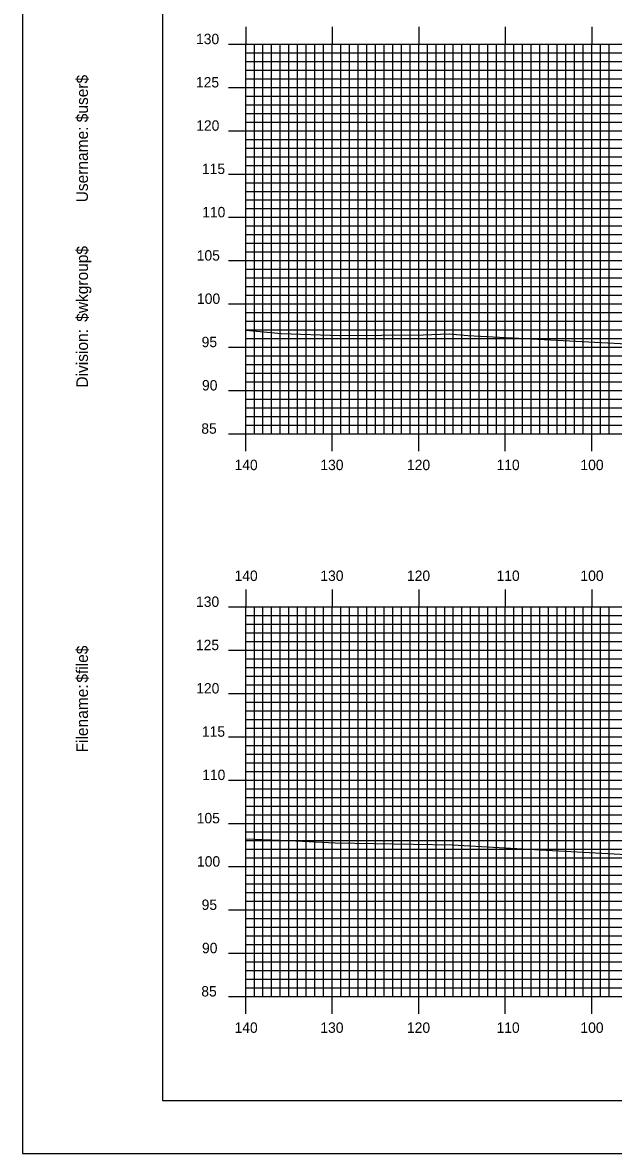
# Model space of a CAD drawing. Extents: x 1785795 to 1786139, y 442591 to 442811.
# Drawn here: x 1785795.3 to 1785863.6, y 442590.5 to 442721.2 of the extents above; entities that cross this region are included whole.
import ezdxf

# ---------------------------------------------------------------- set-up
doc = ezdxf.new("R2010")
doc.units = 0
for name, color, linetype in [('BORDER', 7, 'Continuous'), ('H_V ANNOTATION', 7, 'Continuous'), ('MAJOR', 7, 'Continuous'), ('MINOR', 7, 'Continuous'), ('PLOT BOUNDARY', 7, 'Continuous'), ('S_Roadway_Centerline', 7, 'Continuous')]:
    doc.layers.add(name, color=color, linetype=linetype)

msp = doc.modelspace()

# ---------------------------------------------------------------- linework, layer by layer
at = {"layer": 'BORDER'}
msp.add_lwpolyline([(1785811.45, 442596.67), (1786131.45, 442596.67), (1786131.45, 442806.67), (1785811.45, 442806.67)], close=True, dxfattribs=at)
at = {"layer": 'MAJOR'}
for p, q in [((1785821.05, 442720.67), (1785821.05, 442718.67)), ((1785831.05, 442720.67), (1785831.05, 442718.67)), ((1785841.05, 442720.67), (1785841.05, 442718.67)), ((1785851.05, 442720.67), (1785851.05, 442718.67)), ((1785861.05, 442720.67), (1785861.05, 442718.67)), ((1785819.05, 442718.67), (1785821.05, 442718.67)), ((1785821.05, 442718.67), (1786101.05, 442718.67)), ((1785821.05, 442673.67), (1785821.05, 442718.67)), ((1785821.05, 442673.67), (1785821.05, 442718.67)), ((1785821.05, 442718.67), (1786101.05, 442718.67)), ((1785831.05, 442673.67), (1785831.05, 442718.67)), ((1785841.05, 442673.67), (1785841.05, 442718.67)), ((1785851.05, 442673.67), (1785851.05, 442718.67)), ((1785861.05, 442673.67), (1785861.05, 442718.67)), ((1785819.05, 442713.67), (1785821.05, 442713.67)), ((1785821.05, 442713.67), (1786101.05, 442713.67)), ((1785819.05, 442708.67), (1785821.05, 442708.67)), ((1785821.05, 442708.67), (1786101.05, 442708.67)), ((1785819.05, 442703.67), (1785821.05, 442703.67)), ((1785821.05, 442703.67), (1786101.05, 442703.67)), ((1785819.05, 442698.67), (1785821.05, 442698.67)), ((1785821.05, 442698.67), (1786101.05, 442698.67)), ((1785819.05, 442693.67), (1785821.05, 442693.67)), ((1785821.05, 442693.67), (1786101.05, 442693.67)), ((1785819.05, 442688.67), (1785821.05, 442688.67)), ((1785821.05, 442688.67), (1786101.05, 442688.67)), ((1785819.05, 442683.67), (1785821.05, 442683.67)), ((1785821.05, 442683.67), (1786101.05, 442683.67)), ((1785819.05, 442678.67), (1785821.05, 442678.67)), ((1785821.05, 442678.67), (1786101.05, 442678.67)), ((1785819.05, 442673.67), (1785821.05, 442673.67)), ((1785821.05, 442673.67), (1786101.05, 442673.67)), ((1785821.05, 442673.67), (1786101.05, 442673.67)), ((1785821.05, 442671.66), (1785821.05, 442673.67)), ((1785831.05, 442671.66), (1785831.05, 442673.67)), ((1785841.05, 442671.66), (1785841.05, 442673.67)), ((1785851.05, 442671.66), (1785851.05, 442673.67)), ((1785861.05, 442671.66), (1785861.05, 442673.67)), ((1785821.05, 442655.67), (1785821.05, 442653.67)), ((1785831.05, 442655.67), (1785831.05, 442653.67)), ((1785841.05, 442655.67), (1785841.05, 442653.67)), ((1785851.05, 442655.67), (1785851.05, 442653.67)), ((1785861.05, 442655.67), (1785861.05, 442653.67)), ((1785819.05, 442653.67), (1785821.05, 442653.67)), ((1785821.05, 442653.67), (1786101.05, 442653.67)), ((1785821.05, 442608.67), (1785821.05, 442653.67)), ((1785821.05, 442608.67), (1785821.05, 442653.67)), ((1785821.05, 442653.67), (1786101.05, 442653.67)), ((1785831.05, 442608.67), (1785831.05, 442653.67)), ((1785841.05, 442608.67), (1785841.05, 442653.67)), ((1785851.05, 442608.67), (1785851.05, 442653.67)), ((1785861.05, 442608.67), (1785861.05, 442653.67)), ((1785819.05, 442648.67), (1785821.05, 442648.67)), ((1785821.05, 442648.67), (1786101.05, 442648.67)), ((1785819.05, 442643.67), (1785821.05, 442643.67)), ((1785821.05, 442643.67), (1786101.05, 442643.67)), ((1785819.05, 442638.67), (1785821.05, 442638.67)), ((1785821.05, 442638.67), (1786101.05, 442638.67)), ((1785819.05, 442633.67), (1785821.05, 442633.67)), ((1785821.05, 442633.67), (1786101.05, 442633.67)), ((1785819.05, 442628.67), (1785821.05, 442628.67)), ((1785821.05, 442628.67), (1786101.05, 442628.67)), ((1785819.05, 442623.67), (1785821.05, 442623.67)), ((1785821.05, 442623.67), (1786101.05, 442623.67)), ((1785819.05, 442618.67), (1785821.05, 442618.67)), ((1785821.05, 442618.67), (1786101.05, 442618.67)), ((1785819.05, 442613.67), (1785821.05, 442613.67)), ((1785821.05, 442613.67), (1786101.05, 442613.67)), ((1785819.05, 442608.67), (1785821.05, 442608.67)), ((1785821.05, 442608.67), (1786101.05, 442608.67)), ((1785821.05, 442608.67), (1786101.05, 442608.67)), ((1785821.05, 442606.66), (1785821.05, 442608.67)), ((1785831.05, 442606.66), (1785831.05, 442608.67)), ((1785841.05, 442606.66), (1785841.05, 442608.67)), ((1785851.05, 442606.66), (1785851.05, 442608.67)), ((1785861.05, 442606.66), (1785861.05, 442608.67))]:
    msp.add_line(p, q, dxfattribs=at)
at = {"layer": 'MINOR'}
for p, q in [((1785822.05, 442673.67), (1785822.05, 442718.67)), ((1785823.05, 442673.67), (1785823.05, 442718.67)), ((1785824.05, 442673.67), (1785824.05, 442718.67)), ((1785825.05, 442673.67), (1785825.05, 442718.67)), ((1785826.05, 442673.67), (1785826.05, 442718.67)), ((1785827.05, 442673.67), (1785827.05, 442718.67)), ((1785828.05, 442673.67), (1785828.05, 442718.67)), ((1785829.05, 442673.67), (1785829.05, 442718.67)), ((1785830.05, 442673.67), (1785830.05, 442718.67)), ((1785832.05, 442673.67), (1785832.05, 442718.67)), ((1785833.05, 442673.67), (1785833.05, 442718.67)), ((1785834.05, 442673.67), (1785834.05, 442718.67)), ((1785835.05, 442673.67), (1785835.05, 442718.67)), ((1785836.05, 442673.67), (1785836.05, 442718.67)), ((1785837.05, 442673.67), (1785837.05, 442718.67)), ((1785838.05, 442673.67), (1785838.05, 442718.67)), ((1785839.05, 442673.67), (1785839.05, 442718.67)), ((1785840.05, 442673.67), (1785840.05, 442718.67)), ((1785842.05, 442673.67), (1785842.05, 442718.67)), ((1785843.05, 442673.67), (1785843.05, 442718.67)), ((1785844.05, 442673.67), (1785844.05, 442718.67)), ((1785845.05, 442673.67), (1785845.05, 442718.67)), ((1785846.05, 442673.67), (1785846.05, 442718.67)), ((1785847.05, 442673.67), (1785847.05, 442718.67)), ((1785848.05, 442673.67), (1785848.05, 442718.67)), ((1785849.05, 442673.67), (1785849.05, 442718.67)), ((1785850.05, 442673.67), (1785850.05, 442718.67)), ((1785852.05, 442673.67), (1785852.05, 442718.67)), ((1785853.05, 442673.67), (1785853.05, 442718.67)), ((1785854.05, 442673.67), (1785854.05, 442718.67)), ((1785855.05, 442673.67), (1785855.05, 442718.67)), ((1785856.05, 442673.67), (1785856.05, 442718.67)), ((1785857.05, 442673.67), (1785857.05, 442718.67)), ((1785858.05, 442673.67), (1785858.05, 442718.67)), ((1785859.05, 442673.67), (1785859.05, 442718.67)), ((1785860.05, 442673.67), (1785860.05, 442718.67)), ((1785862.05, 442673.67), (1785862.05, 442718.67)), ((1785863.05, 442673.67), (1785863.05, 442718.67)), ((1785821.05, 442717.67), (1786101.05, 442717.67)), ((1785821.05, 442717.67), (1785823.06, 442717.67)), ((1785821.05, 442716.67), (1786101.05, 442716.67)), ((1785821.05, 442716.67), (1785823.06, 442716.67)), ((1785821.05, 442715.67), (1786101.05, 442715.67)), ((1785821.05, 442715.67), (1785823.06, 442715.67)), ((1785821.05, 442714.67), (1786101.05, 442714.67)), ((1785821.05, 442714.67), (1785823.06, 442714.67)), ((1785821.05, 442712.67), (1786101.05, 442712.67)), ((1785821.05, 442712.67), (1785823.06, 442712.67)), ((1785821.05, 442711.67), (1786101.05, 442711.67)), ((1785821.05, 442711.67), (1785823.06, 442711.67)), ((1785821.05, 442710.67), (1786101.05, 442710.67)), ((1785821.05, 442710.67), (1785823.06, 442710.67)), ((1785821.05, 442709.67), (1786101.05, 442709.67)), ((1785821.05, 442709.67), (1785823.06, 442709.67)), ((1785821.05, 442707.67), (1786101.05, 442707.67)), ((1785821.05, 442707.67), (1785823.06, 442707.67)), ((1785821.05, 442706.67), (1786101.05, 442706.67)), ((1785821.05, 442706.67), (1785823.06, 442706.67)), ((1785821.05, 442705.67), (1786101.05, 442705.67)), ((1785821.05, 442705.67), (1785823.06, 442705.67)), ((1785821.05, 442704.67), (1786101.05, 442704.67)), ((1785821.05, 442704.67), (1785823.06, 442704.67)), ((1785821.05, 442702.67), (1786101.05, 442702.67)), ((1785821.05, 442702.67), (1785823.06, 442702.67)), ((1785821.05, 442701.67), (1786101.05, 442701.67)), ((1785821.05, 442701.67), (1785823.06, 442701.67)), ((1785821.05, 442700.67), (1786101.05, 442700.67)), ((1785821.05, 442700.67), (1785823.06, 442700.67)), ((1785821.05, 442699.67), (1786101.05, 442699.67)), ((1785821.05, 442699.67), (1785823.06, 442699.67)), ((1785821.05, 442697.67), (1786101.05, 442697.67)), ((1785821.05, 442697.67), (1785823.06, 442697.67)), ((1785821.05, 442696.67), (1786101.05, 442696.67)), ((1785821.05, 442696.67), (1785823.06, 442696.67)), ((1785821.05, 442695.67), (1786101.05, 442695.67)), ((1785821.05, 442695.67), (1785823.06, 442695.67)), ((1785821.05, 442694.67), (1786101.05, 442694.67)), ((1785821.05, 442694.67), (1785823.06, 442694.67)), ((1785821.05, 442692.67), (1786101.05, 442692.67)), ((1785821.05, 442692.67), (1785823.06, 442692.67)), ((1785821.05, 442691.67), (1786101.05, 442691.67)), ((1785821.05, 442691.67), (1785823.06, 442691.67)), ((1785821.05, 442690.67), (1786101.05, 442690.67)), ((1785821.05, 442690.67), (1785823.06, 442690.67)), ((1785821.05, 442689.67), (1786101.05, 442689.67)), ((1785821.05, 442689.67), (1785823.06, 442689.67)), ((1785821.05, 442687.67), (1786101.05, 442687.67)), ((1785821.05, 442687.67), (1785823.06, 442687.67)), ((1785821.05, 442686.67), (1786101.05, 442686.67)), ((1785821.05, 442686.67), (1785823.06, 442686.67)), ((1785821.05, 442685.67), (1786101.05, 442685.67)), ((1785821.05, 442685.67), (1785823.06, 442685.67)), ((1785821.05, 442684.67), (1786101.05, 442684.67)), ((1785821.05, 442684.67), (1785823.06, 442684.67)), ((1785821.05, 442682.67), (1786101.05, 442682.67)), ((1785821.05, 442682.67), (1785823.06, 442682.67)), ((1785821.05, 442681.67), (1786101.05, 442681.67)), ((1785821.05, 442681.67), (1785823.06, 442681.67)), ((1785821.05, 442680.67), (1786101.05, 442680.67)), ((1785821.05, 442680.67), (1785823.06, 442680.67)), ((1785821.05, 442679.67), (1786101.05, 442679.67)), ((1785821.05, 442679.67), (1785823.06, 442679.67)), ((1785821.05, 442677.67), (1786101.05, 442677.67)), ((1785821.05, 442677.67), (1785823.06, 442677.67)), ((1785821.05, 442676.67), (1786101.05, 442676.67)), ((1785821.05, 442676.67), (1785823.06, 442676.67)), ((1785821.05, 442675.67), (1786101.05, 442675.67)), ((1785821.05, 442675.67), (1785823.06, 442675.67)), ((1785821.05, 442674.67), (1786101.05, 442674.67)), ((1785821.05, 442674.67), (1785823.06, 442674.67)), ((1785821.05, 442652.67), (1786101.05, 442652.67)), ((1785821.05, 442652.67), (1785823.06, 442652.67)), ((1785822.05, 442608.67), (1785822.05, 442653.67)), ((1785823.05, 442608.67), (1785823.05, 442653.67)), ((1785824.05, 442608.67), (1785824.05, 442653.67)), ((1785825.05, 442608.67), (1785825.05, 442653.67)), ((1785826.05, 442608.67), (1785826.05, 442653.67)), ((1785827.05, 442608.67), (1785827.05, 442653.67)), ((1785828.05, 442608.67), (1785828.05, 442653.67)), ((1785829.05, 442608.67), (1785829.05, 442653.67)), ((1785830.05, 442608.67), (1785830.05, 442653.67)), ((1785832.05, 442608.67), (1785832.05, 442653.67)), ((1785833.05, 442608.67), (1785833.05, 442653.67)), ((1785834.05, 442608.67), (1785834.05, 442653.67)), ((1785835.05, 442608.67), (1785835.05, 442653.67)), ((1785836.05, 442608.67), (1785836.05, 442653.67)), ((1785837.05, 442608.67), (1785837.05, 442653.67)), ((1785838.05, 442608.67), (1785838.05, 442653.67)), ((1785839.05, 442608.67), (1785839.05, 442653.67)), ((1785840.05, 442608.67), (1785840.05, 442653.67)), ((1785842.05, 442608.67), (1785842.05, 442653.67)), ((1785843.05, 442608.67), (1785843.05, 442653.67)), ((1785844.05, 442608.67), (1785844.05, 442653.67)), ((1785845.05, 442608.67), (1785845.05, 442653.67)), ((1785846.05, 442608.67), (1785846.05, 442653.67)), ((1785847.05, 442608.67), (1785847.05, 442653.67)), ((1785848.05, 442608.67), (1785848.05, 442653.67)), ((1785849.05, 442608.67), (1785849.05, 442653.67)), ((1785850.05, 442608.67), (1785850.05, 442653.67)), ((1785852.05, 442608.67), (1785852.05, 442653.67)), ((1785853.05, 442608.67), (1785853.05, 442653.67)), ((1785854.05, 442608.67), (1785854.05, 442653.67)), ((1785855.05, 442608.67), (1785855.05, 442653.67)), ((1785856.05, 442608.67), (1785856.05, 442653.67)), ((1785857.05, 442608.67), (1785857.05, 442653.67)), ((1785858.05, 442608.67), (1785858.05, 442653.67)), ((1785859.05, 442608.67), (1785859.05, 442653.67)), ((1785860.05, 442608.67), (1785860.05, 442653.67)), ((1785862.05, 442608.67), (1785862.05, 442653.67)), ((1785863.05, 442608.67), (1785863.05, 442653.67)), ((1785821.05, 442651.67), (1786101.05, 442651.67)), ((1785821.05, 442651.67), (1785823.06, 442651.67)), ((1785821.05, 442650.67), (1786101.05, 442650.67)), ((1785821.05, 442650.67), (1785823.06, 442650.67)), ((1785821.05, 442649.67), (1786101.05, 442649.67)), ((1785821.05, 442649.67), (1785823.06, 442649.67)), ((1785821.05, 442647.67), (1786101.05, 442647.67)), ((1785821.05, 442647.67), (1785823.06, 442647.67)), ((1785821.05, 442646.67), (1786101.05, 442646.67)), ((1785821.05, 442646.67), (1785823.06, 442646.67)), ((1785821.05, 442645.67), (1786101.05, 442645.67)), ((1785821.05, 442645.67), (1785823.06, 442645.67)), ((1785821.05, 442644.67), (1786101.05, 442644.67)), ((1785821.05, 442644.67), (1785823.06, 442644.67)), ((1785821.05, 442642.67), (1786101.05, 442642.67)), ((1785821.05, 442642.67), (1785823.06, 442642.67)), ((1785821.05, 442641.67), (1786101.05, 442641.67)), ((1785821.05, 442641.67), (1785823.06, 442641.67)), ((1785821.05, 442640.67), (1786101.05, 442640.67)), ((1785821.05, 442640.67), (1785823.06, 442640.67)), ((1785821.05, 442639.67), (1786101.05, 442639.67)), ((1785821.05, 442639.67), (1785823.06, 442639.67)), ((1785821.05, 442637.67), (1786101.05, 442637.67)), ((1785821.05, 442637.67), (1785823.06, 442637.67)), ((1785821.05, 442636.67), (1786101.05, 442636.67)), ((1785821.05, 442636.67), (1785823.06, 442636.67)), ((1785821.05, 442635.67), (1786101.05, 442635.67)), ((1785821.05, 442635.67), (1785823.06, 442635.67)), ((1785821.05, 442634.67), (1786101.05, 442634.67)), ((1785821.05, 442634.67), (1785823.06, 442634.67)), ((1785821.05, 442632.67), (1786101.05, 442632.67)), ((1785821.05, 442632.67), (1785823.06, 442632.67)), ((1785821.05, 442631.67), (1786101.05, 442631.67)), ((1785821.05, 442631.67), (1785823.06, 442631.67)), ((1785821.05, 442630.67), (1786101.05, 442630.67)), ((1785821.05, 442630.67), (1785823.06, 442630.67)), ((1785821.05, 442629.67), (1786101.05, 442629.67)), ((1785821.05, 442629.67), (1785823.06, 442629.67)), ((1785821.05, 442627.67), (1786101.05, 442627.67)), ((1785821.05, 442627.67), (1785823.06, 442627.67)), ((1785821.05, 442626.67), (1786101.05, 442626.67)), ((1785821.05, 442626.67), (1785823.06, 442626.67)), ((1785821.05, 442625.67), (1786101.05, 442625.67)), ((1785821.05, 442625.67), (1785823.06, 442625.67)), ((1785821.05, 442624.67), (1786101.05, 442624.67)), ((1785821.05, 442624.67), (1785823.06, 442624.67)), ((1785821.05, 442622.67), (1786101.05, 442622.67)), ((1785821.05, 442622.67), (1785823.06, 442622.67)), ((1785821.05, 442621.67), (1786101.05, 442621.67)), ((1785821.05, 442621.67), (1785823.06, 442621.67)), ((1785821.05, 442620.67), (1786101.05, 442620.67)), ((1785821.05, 442620.67), (1785823.06, 442620.67)), ((1785821.05, 442619.67), (1786101.05, 442619.67)), ((1785821.05, 442619.67), (1785823.06, 442619.67)), ((1785821.05, 442617.67), (1786101.05, 442617.67)), ((1785821.05, 442617.67), (1785823.06, 442617.67)), ((1785821.05, 442616.67), (1786101.05, 442616.67)), ((1785821.05, 442616.67), (1785823.06, 442616.67)), ((1785821.05, 442615.67), (1786101.05, 442615.67)), ((1785821.05, 442615.67), (1785823.06, 442615.67)), ((1785821.05, 442614.67), (1786101.05, 442614.67)), ((1785821.05, 442614.67), (1785823.06, 442614.67)), ((1785821.05, 442612.67), (1786101.05, 442612.67)), ((1785821.05, 442612.67), (1785823.06, 442612.67)), ((1785821.05, 442611.67), (1786101.05, 442611.67)), ((1785821.05, 442611.67), (1785823.06, 442611.67)), ((1785821.05, 442610.67), (1786101.05, 442610.67)), ((1785821.05, 442610.67), (1785823.06, 442610.67)), ((1785821.05, 442609.67), (1786101.05, 442609.67)), ((1785821.05, 442609.67), (1785823.06, 442609.67))]:
    msp.add_line(p, q, dxfattribs=at)
at = {"layer": 'PLOT BOUNDARY'}
msp.add_lwpolyline([(1785795.27, 442590.55), (1786135.27, 442590.55), (1786135.27, 442810.55), (1785795.27, 442810.55)], close=True, dxfattribs=at)
at = {"layer": 'S_Roadway_Centerline'}
for points in [[(1785821.05, 442685.62), (1785825.2, 442685.24), (1785831.92, 442685), (1785841.55, 442685.11), (1785844.55, 442685.23), (1785846.72, 442685.03), (1785866.57, 442683.98), (1785867.35, 442683.98), (1785867.96, 442683.95), (1785879.16, 442683.97), (1785888.49, 442683.28), (1785893.47, 442683.16), (1785902.14, 442683.24), (1785908.71, 442683.02), (1785913.18, 442683), (1785920, 442682.83), (1785931.29, 442682.54), (1785945.81, 442682.06)], [(1785821.05, 442626.89), (1785826.83, 442626.63), (1785831.38, 442626.4), (1785844.92, 442626.2), (1785855.77, 442625.57), (1785865.08, 442625.07), (1785882.98, 442624.39), (1785886.4, 442624.11), (1785896.82, 442623.75), (1785907.15, 442623.13), (1785910.93, 442623.03), (1785918.88, 442623.24), (1785927.77, 442622.64), (1785931.69, 442622.46), (1785935.23, 442622.34)]]:
    msp.add_lwpolyline(points, dxfattribs=at)

# ---------------------------------------------------------------- texts
at = {"layer": 'BORDER'}
for s, p in [('$user$', (1785802.82, 442709.65)), ('Username:', (1785802.82, 442700.4)), ('$wkgroup$', (1785802.82, 442686.6)), ('Division:', (1785802.82, 442679)), ('$file$', (1785802.82, 442644.92)), ('Filename:', (1785802.82, 442636.86))]:
    msp.add_text(s, height=1.339, rotation=90, dxfattribs=at).set_placement(p)
at = {"layer": 'H_V ANNOTATION'}
for s, p in [('130', (1785815.31, 442718.67)), ('125', (1785815.3, 442713.67)), ('120', (1785815.33, 442708.67)), ('115', (1785815.99, 442703.67)), ('110', (1785816.02, 442698.67)), ('105', (1785815.39, 442693.67)), ('100', (1785815.42, 442688.67)), ('95', (1785815.96, 442683.67)), ('90', (1785816, 442678.67)), ('85', (1785815.92, 442673.67)), ('140', (1785819.76, 442669.47)), ('130', (1785829.68, 442669.47)), ('120', (1785839.69, 442669.47)), ('110', (1785850.04, 442669.47)), ('100', (1785859.74, 442669.47)), ('140', (1785819.76, 442656.67)), ('130', (1785829.68, 442656.67)), ('120', (1785839.69, 442656.67)), ('110', (1785850.04, 442656.67)), ('100', (1785859.74, 442656.67)), ('130', (1785815.31, 442653.67)), ('125', (1785815.3, 442648.67)), ('120', (1785815.33, 442643.67)), ('115', (1785815.99, 442638.67)), ('110', (1785816.02, 442633.67)), ('105', (1785815.39, 442628.67)), ('100', (1785815.42, 442623.67)), ('95', (1785815.96, 442618.67)), ('90', (1785816, 442613.67)), ('85', (1785815.92, 442608.67)), ('140', (1785819.76, 442604.47)), ('130', (1785829.68, 442604.47)), ('120', (1785839.69, 442604.47)), ('110', (1785850.04, 442604.47)), ('100', (1785859.74, 442604.47))]:
    msp.add_text(s, height=1.2, dxfattribs=at).set_placement(p)
at = {"layer": 'MAJOR'}
for p in [(1785821.04, 442673.67), (1785821.04, 442608.67)]:
    msp.add_text('-', height=0.012, dxfattribs=at).set_placement(p)

doc.saveas('drawing.dxf')
